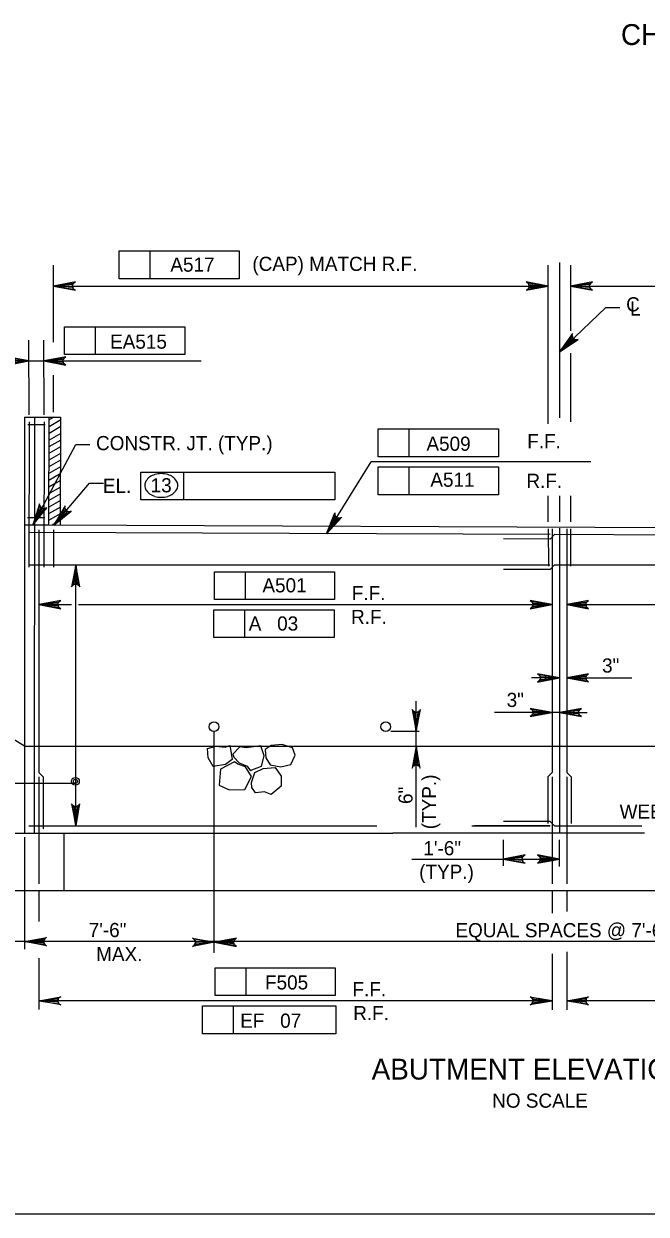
# Model space of a CAD drawing. Extents: x 638255 to 640306, y 296059 to 298435.
# Drawn here: x 638652.6 to 638784.6, y 296668.5 to 296920.7 of the extents above; entities that cross this region are included whole.
import ezdxf

# ---------------------------------------------------------------- set-up
doc = ezdxf.new("R2010")
doc.units = 0
for name, color, linetype in [('2', 7, 'Continuous'), ('4', 7, 'Continuous'), ('Level 10', 7, 'Continuous'), ('Level 3', 7, 'Continuous'), ('Level 4', 7, 'Continuous'), ('Level 5', 7, 'Continuous')]:
    doc.layers.add(name, color=color, linetype=linetype)

# ---------------------------------------------------------------- blocks, each defined once
blk = doc.blocks.new('ROCK')
at = {"layer": '4'}
for points in [[(2.36725, 1.088), (2.2065, 0.82625), (2.378625, 0.506625), (2.66975, 0.3095), (3.128875, 0.403375), (3.48475, 0.6775), (3.4915, 1.123375), (3.25625, 1.36725), (2.783625, 1.308375)], [(1.10175, -0.02725), (1.4015, -0.159125), (1.78825, -0.148875), (1.980875, -0.266), (2.343375, 0.09475), (2.27875, 0.5505), (1.969375, 0.883), (1.4225, 0.553625), (1.152875, 0.479), (1.0105, 0.082)], [(0.74675, 0.359875), (0.882, 0.16), (1.072875, -0.144), (0.892, -0.457375), (0.448125, -0.758625), (0.1, -0.49325), (-0.095, -0.146375), (0.202875, 0.1025), (0.579125, 0.219875)], [(2.231375, -0.71725), (2.2025, -0.266375), (2.45475, 0.037125), (2.9085, 0.28875), (3.2995, 0.047625), (3.46875, -0.344), (3.231625, -0.855), (2.92, -0.860375), (2.5765, -1.054625), (2.340375, -0.904375)], [(1.2085, -0.192875), (0.778375, -0.737625), (1.008375, -1.391375), (1.48725, -1.396875), (2.09825, -1.106625), (2.133375, -0.486375), (1.723125, -0.203375), (1.37425, -0.239875)]]:
    blk.add_lwpolyline(points, close=True, dxfattribs=at)

msp = doc.modelspace()

# ---------------------------------------------------------------- linework, layer by layer
at = {"layer": '2'}
msp.add_line((639261.46, 296668.46), (638475.46, 296668.46), dxfattribs=at)
at = {"layer": 'Level 10'}
for p, q in [((638766.19, 296870.09), (638766.19, 296837.19)), ((638652.78, 296837.33), (638660.4, 296837.33)), ((638652.78, 296837.33), (638652.78, 296749.22)), ((638654.87, 296837.33), (638654.8, 296749.22)), ((638657.93, 296837.33), (638657.87, 296814.43)), ((638659.01, 296837.33), (638657.98, 296836.73)), ((638660.4, 296837.33), (638660.34, 296814.42)), ((638660.45, 296836.74), (638657.97, 296835.31)), ((638660.44, 296835.32), (638657.97, 296833.89)), ((638660.43, 296832.48), (638657.95, 296831.05)), ((638660.44, 296833.9), (638657.96, 296832.47)), ((638660.41, 296829.63), (638657.94, 296828.2)), ((638660.42, 296831.05), (638657.95, 296829.62)), ((638660.41, 296828.21), (638657.93, 296826.78)), ((638660.4, 296826.79), (638657.92, 296825.36)), ((638660.33, 296825.33), (638657.92, 296823.94)), ((638660.39, 296825.37), (638660.33, 296825.33)), ((638659.24, 296823.28), (638657.91, 296822.52)), ((638660.38, 296822.52), (638658.15, 296821.23)), ((638660.39, 296823.94), (638659.24, 296823.28)), ((638660.36, 296819.68), (638657.89, 296818.25)), ((638658.15, 296821.23), (638657.9, 296821.09)), ((638660.37, 296821.1), (638657.9, 296819.67)), ((638766.19, 296820.68), (638766.19, 296815.16)), ((638660.35, 296816.83), (638657.87, 296815.4)), ((638660.36, 296818.26), (638657.88, 296816.83)), ((638657.87, 296814.43), (638652.66, 296814.45)), ((638874.5, 296813.51), (638657.87, 296814.43)), ((638660.34, 296815.41), (638658.64, 296814.43)), ((638766.19, 296813.82), (638766.19, 296749.22)), ((638652.78, 296767.64), (638586.09, 296808.17)), ((638652.66, 296767.64), (638672.04, 296767.64)), ((638672.04, 296767.64), (638881.45, 296767.64)), ((638583.02, 296749.22), (638730.85, 296749.22)), ((638661.13, 296749.22), (638661.13, 296736.95)), ((638730.85, 296749.23), (638784.21, 296749.23)), ((638963.51, 296736.95), (638583.02, 296736.95))]:
    msp.add_line(p, q, dxfattribs=at)
at = {"layer": 'Level 3'}
for p, q in [((638672.82, 296872.56), (638698.31, 296872.56)), ((638672.82, 296866.67), (638672.82, 296872.56)), ((638679.4, 296866.67), (638679.4, 296872.56)), ((638698.31, 296872.56), (638698.31, 296866.67)), ((638658.88, 296853.2), (638658.88, 296869.52)), ((638763.82, 296835.89), (638763.82, 296869.53)), ((638768.53, 296869.53), (638768.53, 296855.61)), ((638658.88, 296865.1), (638763.82, 296865.1)), ((638698.31, 296866.67), (638672.82, 296866.67)), ((638768.53, 296865.1), (638873.48, 296865.1)), ((638766.19, 296851.19), (638776.04, 296860.56)), ((638776.04, 296860.56), (638778.98, 296860.56)), ((638661.24, 296856.47), (638686.73, 296856.47)), ((638661.24, 296850.58), (638661.24, 296856.47)), ((638667.82, 296850.58), (638667.82, 296856.47)), ((638686.73, 296856.47), (638686.73, 296850.58)), ((638653.75, 296837.84), (638653.69, 296853.66)), ((638656.91, 296837.84), (638656.85, 296853.66)), ((638686.73, 296850.58), (638661.24, 296850.58)), ((638768.53, 296850.86), (638768.53, 296836.32)), ((638653.71, 296849.24), (638647.79, 296849.24)), ((638653.69, 296849.24), (638656.85, 296849.24)), ((638656.87, 296849.24), (638690.24, 296849.24)), ((638659.78, 296849.24), (638662.73, 296849.24)), ((638659.79, 296849.24), (638662.74, 296849.24)), ((638662.32, 296849.24), (638665.27, 296849.24)), ((638658.88, 296838.37), (638658.88, 296846.19)), ((638727.76, 296834.84), (638753.25, 296834.84)), ((638727.76, 296828.95), (638727.76, 296834.84)), ((638734.34, 296828.95), (638734.34, 296834.84)), ((638753.25, 296834.84), (638753.25, 296828.95)), ((638654.53, 296814.44), (638663.64, 296831.54)), ((638663.64, 296831.54), (638666.58, 296831.54)), ((638716.83, 296812.64), (638726.27, 296827.86)), ((638772.83, 296827.86), (638726.27, 296827.86)), ((638753.25, 296828.95), (638727.76, 296828.95)), ((638677.4, 296825.7), (638686.55, 296825.7)), ((638677.4, 296819.8), (638677.4, 296825.7)), ((638686.55, 296819.8), (638686.55, 296825.7)), ((638686.55, 296825.7), (638718.53, 296825.7)), ((638718.53, 296825.7), (638718.53, 296819.8)), ((638727.76, 296826.77), (638753.25, 296826.77)), ((638727.76, 296820.88), (638727.76, 296826.77)), ((638734.34, 296820.88), (638734.34, 296826.77)), ((638753.25, 296826.77), (638753.25, 296820.88)), ((638659.01, 296814.42), (638666.55, 296823.34)), ((638666.55, 296823.34), (638669.5, 296823.34)), ((638718.53, 296819.8), (638677.4, 296819.8)), ((638753.25, 296820.88), (638727.76, 296820.88)), ((638763.82, 296815.15), (638763.82, 296820.68)), ((638768.53, 296820.68), (638768.53, 296815.15)), ((638663.62, 296778.9), (638663.62, 296806.02)), ((638693.02, 296804.59), (638718.51, 296804.59)), ((638693.02, 296798.69), (638693.02, 296804.59)), ((638699.6, 296798.69), (638699.6, 296804.59)), ((638718.51, 296804.59), (638718.51, 296798.69)), ((638655.78, 296797.6), (638662.72, 296797.6)), ((638664.23, 296797.6), (638764.66, 296797.6)), ((638718.51, 296798.69), (638693.02, 296798.69)), ((638767.73, 296797.6), (638867.1, 296797.6)), ((638692.92, 296790.63), (638692.92, 296796.52)), ((638692.92, 296796.52), (638718.41, 296796.52)), ((638699.51, 296790.63), (638699.51, 296796.52)), ((638718.41, 296796.52), (638718.41, 296790.63)), ((638718.41, 296790.63), (638692.92, 296790.63)), ((638766.19, 296782.09), (638760.3, 296782.09)), ((638767.73, 296782.09), (638781.57, 296782.09)), ((638663.62, 296750.76), (638663.62, 296778.9)), ((638735.82, 296750.43), (638735.82, 296777.18)), ((638758.77, 296774.75), (638752.41, 296774.75)), ((638764.66, 296774.75), (638758.77, 296774.75)), ((638766.19, 296774.75), (638764.66, 296774.75)), ((638766.19, 296774.75), (638772.09, 296774.75)), ((638736.42, 296770.72), (638730.47, 296770.72)), ((638601.92, 296759.8), (638663.62, 296759.8)), ((638652.78, 296748.37), (638652.78, 296724.6)), ((638754.3, 296742.27), (638754.3, 296747.77)), ((638766.19, 296742.13), (638766.19, 296747.77)), ((638734.92, 296743.69), (638766.19, 296743.69)), ((638655.78, 296736.95), (638655.78, 296730.47)), ((638764.66, 296736.95), (638764.66, 296732.23)), ((638767.73, 296736.95), (638767.73, 296732.58)), ((638884.76, 296726.21), (638599.26, 296726.21)), ((638764.66, 296723.64), (638764.66, 296711.76)), ((638767.73, 296724.07), (638767.73, 296711.76)), ((638767.73, 296723.91), (638767.73, 296722.19)), ((638655.78, 296722.7), (638655.78, 296711.85)), ((638764.66, 296723.21), (638764.66, 296722.19)), ((638693.18, 296714.76), (638693.18, 296720.65)), ((638693.18, 296720.65), (638718.67, 296720.65)), ((638699.76, 296714.76), (638699.76, 296720.65)), ((638718.67, 296720.65), (638718.67, 296714.76)), ((638764.66, 296713.67), (638655.78, 296713.67)), ((638718.67, 296714.76), (638693.18, 296714.76)), ((638881.5, 296713.67), (638767.73, 296713.67)), ((638690.53, 296712.59), (638718.76, 296712.59)), ((638690.53, 296706.69), (638690.53, 296712.59)), ((638697.11, 296706.69), (638697.11, 296712.59)), ((638718.76, 296712.59), (638718.76, 296706.69)), ((638718.76, 296706.69), (638690.53, 296706.69))]:
    msp.add_line(p, q, dxfattribs=at)
for points in [[(638658.88, 296865.1), (638663.54, 296864.23), (638663.18, 296864.48), (638662.99, 296864.79), (638662.94, 296865.1), (638662.99, 296865.41), (638663.18, 296865.72), (638663.54, 296865.97), (638658.88, 296865.1), (638663.18, 296865.72), (638662.99, 296865.41), (638658.88, 296865.1), (638662.94, 296865.1), (638662.99, 296864.79), (638658.88, 296865.1), (638663.18, 296864.48)], [(638763.82, 296865.1), (638759.17, 296865.97), (638759.53, 296865.72), (638759.72, 296865.41), (638759.77, 296865.1), (638759.72, 296864.79), (638759.53, 296864.48), (638759.17, 296864.23), (638763.82, 296865.1), (638759.53, 296864.48), (638759.72, 296864.79), (638763.82, 296865.1), (638759.77, 296865.1), (638759.72, 296865.41), (638763.82, 296865.1), (638759.53, 296865.72)], [(638768.53, 296865.1), (638773.18, 296864.23), (638772.83, 296864.48), (638772.64, 296864.79), (638772.59, 296865.1), (638772.64, 296865.41), (638772.83, 296865.72), (638773.18, 296865.97), (638768.53, 296865.1), (638772.83, 296865.72), (638772.64, 296865.41), (638768.53, 296865.1), (638772.59, 296865.1), (638772.64, 296864.79), (638768.53, 296865.1), (638772.83, 296864.48)], [(638766.19, 296851.19), (638770.16, 296853.76), (638769.73, 296853.7), (638769.39, 296853.8), (638769.13, 296853.98), (638768.96, 296854.25), (638768.87, 296854.6), (638768.96, 296855.03), (638766.19, 296851.19), (638768.87, 296854.6), (638768.96, 296854.25), (638766.19, 296851.19), (638769.13, 296853.98), (638769.39, 296853.8), (638766.19, 296851.19), (638769.73, 296853.7)], [(638653.71, 296849.24), (638649.05, 296850.11), (638649.41, 296849.87), (638649.6, 296849.55), (638649.65, 296849.24), (638649.6, 296848.93), (638649.41, 296848.62), (638649.05, 296848.37), (638653.71, 296849.24), (638649.41, 296848.62), (638649.6, 296848.93), (638653.71, 296849.24), (638649.65, 296849.24), (638649.6, 296849.55), (638653.71, 296849.24), (638649.41, 296849.87)], [(638656.87, 296849.24), (638661.52, 296848.37), (638661.16, 296848.62), (638660.97, 296848.93), (638660.92, 296849.24), (638660.97, 296849.55), (638661.16, 296849.87), (638661.52, 296850.11), (638656.87, 296849.24), (638661.16, 296849.87), (638660.97, 296849.55), (638656.87, 296849.24), (638660.92, 296849.24), (638660.97, 296848.93), (638656.87, 296849.24), (638661.16, 296848.62)], [(638654.53, 296814.44), (638657.49, 296818.14), (638657.1, 296817.94), (638656.74, 296817.92), (638656.44, 296818.02), (638656.19, 296818.22), (638656, 296818.53), (638655.95, 296818.96), (638654.53, 296814.44), (638656, 296818.53), (638656.19, 296818.22), (638654.53, 296814.44), (638656.44, 296818.02), (638656.74, 296817.92), (638654.53, 296814.44), (638657.1, 296817.94)], [(638659.01, 296814.42), (638662.68, 296817.41), (638662.26, 296817.3), (638661.9, 296817.36), (638661.63, 296817.52), (638661.43, 296817.76), (638661.31, 296818.11), (638661.35, 296818.54), (638659.01, 296814.42), (638661.31, 296818.11), (638661.43, 296817.76), (638659.01, 296814.42), (638661.63, 296817.52), (638661.9, 296817.36), (638659.01, 296814.42), (638662.26, 296817.3)], [(638716.83, 296812.64), (638718.54, 296817.06), (638718.56, 296816.62), (638718.73, 296816.3), (638718.96, 296816.09), (638719.26, 296815.97), (638719.62, 296815.96), (638720.02, 296816.14), (638716.83, 296812.64), (638719.62, 296815.96), (638719.26, 296815.97), (638716.83, 296812.64), (638718.96, 296816.09), (638718.73, 296816.3), (638716.83, 296812.64), (638718.56, 296816.62)], [(638663.62, 296806.02), (638662.74, 296801.37), (638662.99, 296801.72), (638663.3, 296801.91), (638663.62, 296801.96), (638663.93, 296801.91), (638664.24, 296801.72), (638664.49, 296801.37), (638663.62, 296806.02), (638664.24, 296801.72), (638663.93, 296801.91), (638663.62, 296806.02), (638663.62, 296801.96), (638663.3, 296801.91), (638663.62, 296806.02), (638662.99, 296801.72)], [(638655.78, 296797.6), (638660.43, 296796.73), (638660.07, 296796.98), (638659.88, 296797.29), (638659.83, 296797.6), (638659.88, 296797.91), (638660.07, 296798.23), (638660.43, 296798.47), (638655.78, 296797.6), (638660.07, 296798.23), (638659.88, 296797.91), (638655.78, 296797.6), (638659.83, 296797.6), (638659.88, 296797.29), (638655.78, 296797.6), (638660.07, 296796.98)], [(638764.66, 296797.6), (638760.01, 296798.47), (638760.37, 296798.23), (638760.55, 296797.91), (638760.61, 296797.6), (638760.55, 296797.29), (638760.37, 296796.98), (638760.01, 296796.73), (638764.66, 296797.6), (638760.37, 296796.98), (638760.55, 296797.29), (638764.66, 296797.6), (638760.61, 296797.6), (638760.55, 296797.91), (638764.66, 296797.6), (638760.37, 296798.23)], [(638767.73, 296797.6), (638772.38, 296796.73), (638772.02, 296796.98), (638771.84, 296797.29), (638771.78, 296797.6), (638771.84, 296797.91), (638772.02, 296798.23), (638772.38, 296798.47), (638767.73, 296797.6), (638772.02, 296798.23), (638771.84, 296797.91), (638767.73, 296797.6), (638771.78, 296797.6), (638771.84, 296797.29), (638767.73, 296797.6), (638772.02, 296796.98)], [(638766.19, 296782.09), (638761.54, 296782.96), (638761.9, 296782.71), (638762.09, 296782.4), (638762.14, 296782.09), (638762.09, 296781.77), (638761.9, 296781.46), (638761.54, 296781.21), (638766.19, 296782.09), (638761.9, 296781.46), (638762.09, 296781.77), (638766.19, 296782.09), (638762.14, 296782.09), (638762.09, 296782.4), (638766.19, 296782.09), (638761.9, 296782.71)], [(638767.73, 296782.09), (638772.38, 296781.22), (638772.02, 296781.46), (638771.84, 296781.77), (638771.78, 296782.09), (638771.84, 296782.4), (638772.02, 296782.71), (638772.38, 296782.96), (638767.73, 296782.09), (638772.02, 296782.71), (638771.84, 296782.4), (638767.73, 296782.09), (638771.78, 296782.09), (638771.84, 296781.77), (638767.73, 296782.09), (638772.02, 296781.46)], [(638735.84, 296770.71), (638736.71, 296775.37), (638736.46, 296775.01), (638736.15, 296774.82), (638735.84, 296774.77), (638735.53, 296774.82), (638735.21, 296775.01), (638734.97, 296775.37), (638735.84, 296770.71), (638735.21, 296775.01), (638735.53, 296774.82), (638735.84, 296770.71), (638735.84, 296774.77), (638736.15, 296774.82), (638735.84, 296770.71), (638736.46, 296775.01)], [(638764.66, 296774.75), (638760.01, 296775.63), (638760.37, 296775.38), (638760.55, 296775.07), (638760.61, 296774.75), (638760.55, 296774.44), (638760.37, 296774.13), (638760.01, 296773.88), (638764.66, 296774.75), (638760.37, 296774.13), (638760.55, 296774.44), (638764.66, 296774.75), (638760.61, 296774.75), (638760.55, 296775.07), (638764.66, 296774.75), (638760.37, 296775.38)], [(638766.19, 296774.75), (638770.85, 296773.88), (638770.49, 296774.13), (638770.3, 296774.44), (638770.25, 296774.75), (638770.3, 296775.07), (638770.49, 296775.38), (638770.85, 296775.63), (638766.19, 296774.75), (638770.49, 296775.38), (638770.3, 296775.07), (638766.19, 296774.75), (638770.25, 296774.75), (638770.3, 296774.44), (638766.19, 296774.75), (638770.49, 296774.13)], [(638735.82, 296767.64), (638734.95, 296762.99), (638735.19, 296763.35), (638735.51, 296763.53), (638735.82, 296763.59), (638736.13, 296763.53), (638736.44, 296763.35), (638736.69, 296762.99), (638735.82, 296767.64), (638736.44, 296763.35), (638736.13, 296763.53), (638735.82, 296767.64), (638735.82, 296763.59), (638735.51, 296763.53), (638735.82, 296767.64), (638735.19, 296763.35)], [(638663.62, 296750.76), (638664.49, 296755.41), (638664.24, 296755.05), (638663.93, 296754.87), (638663.62, 296754.81), (638663.3, 296754.87), (638662.99, 296755.05), (638662.74, 296755.41), (638663.62, 296750.76), (638662.99, 296755.05), (638663.3, 296754.87), (638663.62, 296750.76), (638663.62, 296754.81), (638663.93, 296754.87), (638663.62, 296750.76), (638664.24, 296755.05)], [(638754.24, 296743.69), (638758.89, 296742.82), (638758.53, 296743.07), (638758.35, 296743.38), (638758.3, 296743.69), (638758.35, 296744), (638758.53, 296744.31), (638758.89, 296744.56), (638754.24, 296743.69), (638758.53, 296744.31), (638758.35, 296744), (638754.24, 296743.69), (638758.3, 296743.69), (638758.35, 296743.38), (638754.24, 296743.69), (638758.53, 296743.07)], [(638766.19, 296743.69), (638761.54, 296744.56), (638761.9, 296744.31), (638762.09, 296744), (638762.14, 296743.69), (638762.09, 296743.38), (638761.9, 296743.07), (638761.54, 296742.82), (638766.19, 296743.69), (638761.9, 296743.07), (638762.09, 296743.38), (638766.19, 296743.69), (638762.14, 296743.69), (638762.09, 296744), (638766.19, 296743.69), (638761.9, 296744.31)], [(638655.78, 296713.67), (638660.43, 296714.54), (638660.07, 296714.29), (638659.88, 296713.98), (638659.83, 296713.67), (638659.88, 296713.36), (638660.07, 296713.04), (638660.43, 296712.8), (638655.78, 296713.67), (638660.07, 296713.04), (638659.88, 296713.36), (638655.78, 296713.67), (638659.83, 296713.67), (638659.88, 296713.98), (638655.78, 296713.67), (638660.07, 296714.29)], [(638764.66, 296713.67), (638760.01, 296712.8), (638760.37, 296713.04), (638760.55, 296713.36), (638760.61, 296713.67), (638760.55, 296713.98), (638760.37, 296714.29), (638760.01, 296714.54), (638764.66, 296713.67), (638760.37, 296714.29), (638760.55, 296713.98), (638764.66, 296713.67), (638760.61, 296713.67), (638760.55, 296713.36), (638764.66, 296713.67), (638760.37, 296713.04)], [(638767.73, 296713.67), (638772.38, 296714.54), (638772.02, 296714.29), (638771.84, 296713.98), (638771.78, 296713.67), (638771.84, 296713.36), (638772.02, 296713.04), (638772.38, 296712.8), (638767.73, 296713.67), (638772.02, 296713.04), (638771.84, 296713.36), (638767.73, 296713.67), (638771.78, 296713.67), (638771.84, 296713.98), (638767.73, 296713.67), (638772.02, 296714.29)]]:
    msp.add_lwpolyline(points, dxfattribs=at)
for points in [[(638768.68, 296852.85), (638768.01, 296853.56), (638766.19, 296851.19)], [(638650.74, 296849.73), (638650.74, 296848.75), (638653.69, 296849.24)], [(638659.79, 296849.73), (638659.79, 296848.75), (638656.85, 296849.24)], [(638656.35, 296816.81), (638655.49, 296817.28), (638654.53, 296814.44)], [(638661.29, 296816.36), (638660.54, 296816.99), (638659.01, 296814.42)], [(638663.12, 296803.07), (638664.11, 296803.07), (638663.62, 296806.02)], [(638761.71, 296798.1), (638761.71, 296797.11), (638764.66, 296797.6)], [(638770.68, 296798.1), (638770.68, 296797.11), (638767.73, 296797.6)], [(638763.25, 296782.58), (638763.25, 296781.6), (638766.19, 296782.09)], [(638770.68, 296782.58), (638770.68, 296781.6), (638767.73, 296782.09)], [(638761.71, 296775.25), (638761.71, 296774.26), (638764.66, 296774.75)], [(638769.14, 296775.25), (638769.14, 296774.26), (638766.19, 296774.75)], [(638735.32, 296764.7), (638736.31, 296764.7), (638735.82, 296767.64)], [(638663.12, 296753.71), (638664.11, 296753.71), (638663.62, 296750.76)], [(638761.71, 296714.16), (638761.71, 296713.18), (638764.66, 296713.67)], [(638770.68, 296714.16), (638770.68, 296713.18), (638767.73, 296713.67)]]:
    msp.add_lwpolyline(points, close=True, dxfattribs=at)
for centre, radius in [((638692.93, 296771.74), 1.02), ((638729.36, 296771.74), 1.02), ((638663.55, 296760.17), 0.832), ((638663.55, 296760.17), 0.416)]:
    msp.add_circle(centre, radius, dxfattribs=at)
for centre, radius, start, end in [((638680.89, 296822.39), 2.75, 125.6316, 149.9767), ((638681.42, 296821.66), 3.65, 106.5358, 125.6316), ((638681.76, 296820.5), 4.86, 90, 106.5358), ((638681.76, 296820.5), 4.86, 73.4642, 90), ((638682.11, 296821.66), 3.65, 54.3684, 73.4642), ((638682.63, 296822.39), 2.75, 30.0233, 54.3684), ((638680.09, 296822.86), 1.82, 149.9767, 180), ((638680.09, 296822.86), 1.82, 180, 210.0233), ((638680.89, 296823.32), 2.75, 210.0233, 234.3684), ((638682.63, 296823.32), 2.75, 305.6316, 329.9767), ((638683.44, 296822.86), 1.82, 0, 30.0233), ((638683.44, 296822.86), 1.82, 329.9767, 0), ((638681.42, 296824.06), 3.65, 234.3684, 253.4642), ((638681.76, 296825.21), 4.86, 253.4642, 270), ((638681.76, 296825.21), 4.86, 270, 286.5358), ((638682.11, 296824.06), 3.65, 286.5358, 305.6316)]:
    msp.add_arc(centre, radius, start, end, dxfattribs=at)
at = {"layer": 'Level 4'}
for points in [[(638652.78, 296726.21), (638657.43, 296727.08), (638657.07, 296726.83), (638656.89, 296726.52), (638656.83, 296726.21), (638656.89, 296725.9), (638657.07, 296725.58), (638657.43, 296725.34), (638652.78, 296726.21), (638657.07, 296725.58), (638656.89, 296725.9), (638652.78, 296726.21), (638656.83, 296726.21), (638656.89, 296726.52), (638652.78, 296726.21), (638657.07, 296726.83)], [(638693.05, 296726.07), (638688.4, 296725.2), (638688.75, 296725.45), (638688.94, 296725.76), (638688.99, 296726.07), (638688.94, 296726.38), (638688.75, 296726.7), (638688.4, 296726.94), (638693.05, 296726.07), (638688.75, 296726.7), (638688.94, 296726.38), (638693.05, 296726.07), (638688.99, 296726.07), (638688.94, 296725.76), (638693.05, 296726.07), (638688.75, 296725.45)], [(638693.05, 296726.07), (638697.7, 296725.2), (638697.34, 296725.45), (638697.16, 296725.76), (638697.1, 296726.07), (638697.16, 296726.38), (638697.34, 296726.7), (638697.7, 296726.94), (638693.05, 296726.07), (638697.34, 296726.7), (638697.16, 296726.38), (638693.05, 296726.07), (638697.1, 296726.07), (638697.16, 296725.76), (638693.05, 296726.07), (638697.34, 296725.45)]]:
    msp.add_lwpolyline(points, dxfattribs=at)
at = {"layer": 'Level 5'}
for p, q in [((638653.5, 296835.8), (638657.17, 296835.8)), ((638653.75, 296836.31), (638653.69, 296805.51)), ((638656.91, 296836.31), (638656.85, 296805.51)), ((638657.1, 296815.97), (638653.43, 296815.97)), ((638764.23, 296812.44), (638653.69, 296812.91)), ((638655.78, 296813.42), (638655.78, 296762.07)), ((638658.88, 296813.42), (638658.9, 296805.51)), ((638763.82, 296813.65), (638763.84, 296805.74)), ((638765.16, 296812.44), (638764.23, 296811.51)), ((638764.66, 296813.65), (638764.66, 296762.07)), ((638883.62, 296811.93), (638765.16, 296812.44)), ((638767.73, 296813.65), (638767.73, 296762.07)), ((638768.53, 296813.65), (638768.55, 296805.74)), ((638764.23, 296811.51), (638754.3, 296811.55)), ((638653.69, 296806.02), (638764.12, 296806.02)), ((638764.24, 296805.08), (638754.32, 296805.08)), ((638765.17, 296806.02), (638764.24, 296805.08)), ((638765.17, 296806.02), (638883.62, 296806.02)), ((638692.93, 296770.71), (638692.93, 296723.83)), ((638655.78, 296762.07), (638656.71, 296761.14)), ((638764.66, 296762.07), (638763.72, 296761.14)), ((638767.73, 296762.07), (638768.66, 296761.14)), ((638655.78, 296761.14), (638655.78, 296738.48)), ((638656.71, 296761.14), (638656.71, 296750.11)), ((638763.72, 296761.14), (638763.72, 296751.22)), ((638764.66, 296761.14), (638764.66, 296738.48)), ((638767.73, 296761.14), (638767.73, 296738.48)), ((638768.66, 296761.14), (638768.66, 296751.22)), ((638764.24, 296751.69), (638754.32, 296751.69)), ((638765.17, 296750.76), (638764.24, 296751.69)), ((638653.69, 296750.76), (638727.5, 296750.76)), ((638747.62, 296750.76), (638764.12, 296750.76)), ((638764.24, 296750.76), (638748.18, 296750.76)), ((638765.17, 296750.76), (638783.68, 296750.76))]:
    msp.add_line(p, q, dxfattribs=at)

# ---------------------------------------------------------------- block references
at = {"layer": 'Level 3', "xscale": 4.911876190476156, "yscale": 4.911876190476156, "rotation": -23.78336161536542}
msp.add_blockref('ROCK', (638692.26, 296767.59), dxfattribs=at)

# ---------------------------------------------------------------- texts
at = {"layer": 'Level 3'}
for s, height, p in [('CHEEKWALL A DETAIL', 4.4207, (638779.24, 296916.18)), ('A517', 3, (638683.69, 296868.15)), ('(CAP) MATCH R.F.', 3.0001, (638701.08, 296868.31)), ('C', 3, (638780.34, 296859.74)), ('L', 3, (638781.19, 296858.84)), ('EA515', 3, (638670.91, 296851.83)), ('CONSTR. JT. (TYP.)', 3.0001, (638667.93, 296830.33)), ('A509', 3, (638737.99, 296830.2)), ('F.F.', 3, (638759.36, 296830.75)), ('13', 3, (638679.51, 296821.4)), ('A511', 3, (638738.82, 296822.58)), ('R.F.', 3, (638759.19, 296822.34)), ('EL.', 3, (638669.39, 296821.29)), ('A501', 3, (638703.21, 296800.21)), ('F.F.', 3, (638722.17, 296798.56)), ('A   03', 3, (638700.31, 296792.11)), ('R.F.', 3, (638722.01, 296793.5)), ('3"', 3, (638775.23, 296783.21)), ('3"', 3, (638755, 296775.92)), ('WEEPHOLE', 3, (638778.95, 296752.25)), ('1\'-6"', 3, (638737.34, 296744.51)), ('(TYP.)', 3, (638736.45, 296739.51)), ('7\'-6"', 3, (638666.38, 296727.17)), ('EQUAL SPACES @ 7\'-6" MAX.', 3.0001, (638744.14, 296727.13)), ('MAX.', 3, (638667.96, 296722.07)), ('F505', 3, (638703.76, 296716.07)), ('F.F.', 3, (638722.31, 296714.62)), ('EF   07', 3, (638698.5, 296707.96)), ('R.F.', 3, (638722.47, 296709.57)), ('ABUTMENT ELEVATION', 4.4207, (638726.37, 296696.98)), ('NO SCALE', 3, (638751.93, 296691.02))]:
    msp.add_text(s, height=height, dxfattribs=at).set_placement(p)
for s, p in [('(TYP.)', (638740.05, 296750.02)), ('6"', (638735.05, 296755.37))]:
    msp.add_text(s, height=3, rotation=90, dxfattribs=at).set_placement(p)

doc.saveas('drawing.dxf')
